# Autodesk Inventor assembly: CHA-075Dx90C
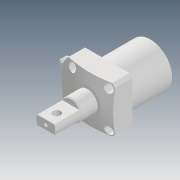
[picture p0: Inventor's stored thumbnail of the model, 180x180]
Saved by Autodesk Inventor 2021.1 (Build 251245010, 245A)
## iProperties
Created: 2019-12
Part Number: CHA-075Dx90C
Description: STEP AP203
Document SubType Name: Assembly
Designer: user
Title: CHA-075Dx90C.STEP
Revision Number: ÈÎºÎ
Sending System: SolidWorks 2017
Preprocessor: SwSTEP 2.0
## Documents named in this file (5)
- D:\Vault_2016\Projekty\Clamptek\Hydraulic\CHA\CHA\CHA-075\Inventor\CHA-075Dx90C\CHA-075Dx90C.iam
- D:\Vault_2016\Projekty\Clamptek\Hydraulic\CHA\CHA\CHA-075\Inventor\CHA-075Dx90C\CHA-075±¾Ìå.ipt
- D:\Vault_2016\Projekty\Clamptek\Hydraulic\CHA\CHA\CHA-075\Inventor\CHA-075Dx90C\G1-4¶ÂÍ·_1.ipt
- D:\Vault_2016\Projekty\Clamptek\Hydraulic\CHA\CHA\CHA-075\Inventor\CHA-075Dx90C\CHA-075D(Ë«±Û£©»îÈû¸Ë_1.ipt
- D:\Vault_2016\Projekty\Clamptek\Hydraulic\CHA\CHA\CHA-075\Inventor\CHA-075Dx90C\CZL20µ÷ËÙ·§_1.iam
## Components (4 placed, 4 different names)
1. CHA-075±¾Ìå_1
2. G1-4¶ÂÍ·_1_2
3. CHA-075D(Ë«±Û£©»îÈû¸Ë_1_3
4. CZL20µ÷ËÙ·§_1_4 [sub-assembly]
